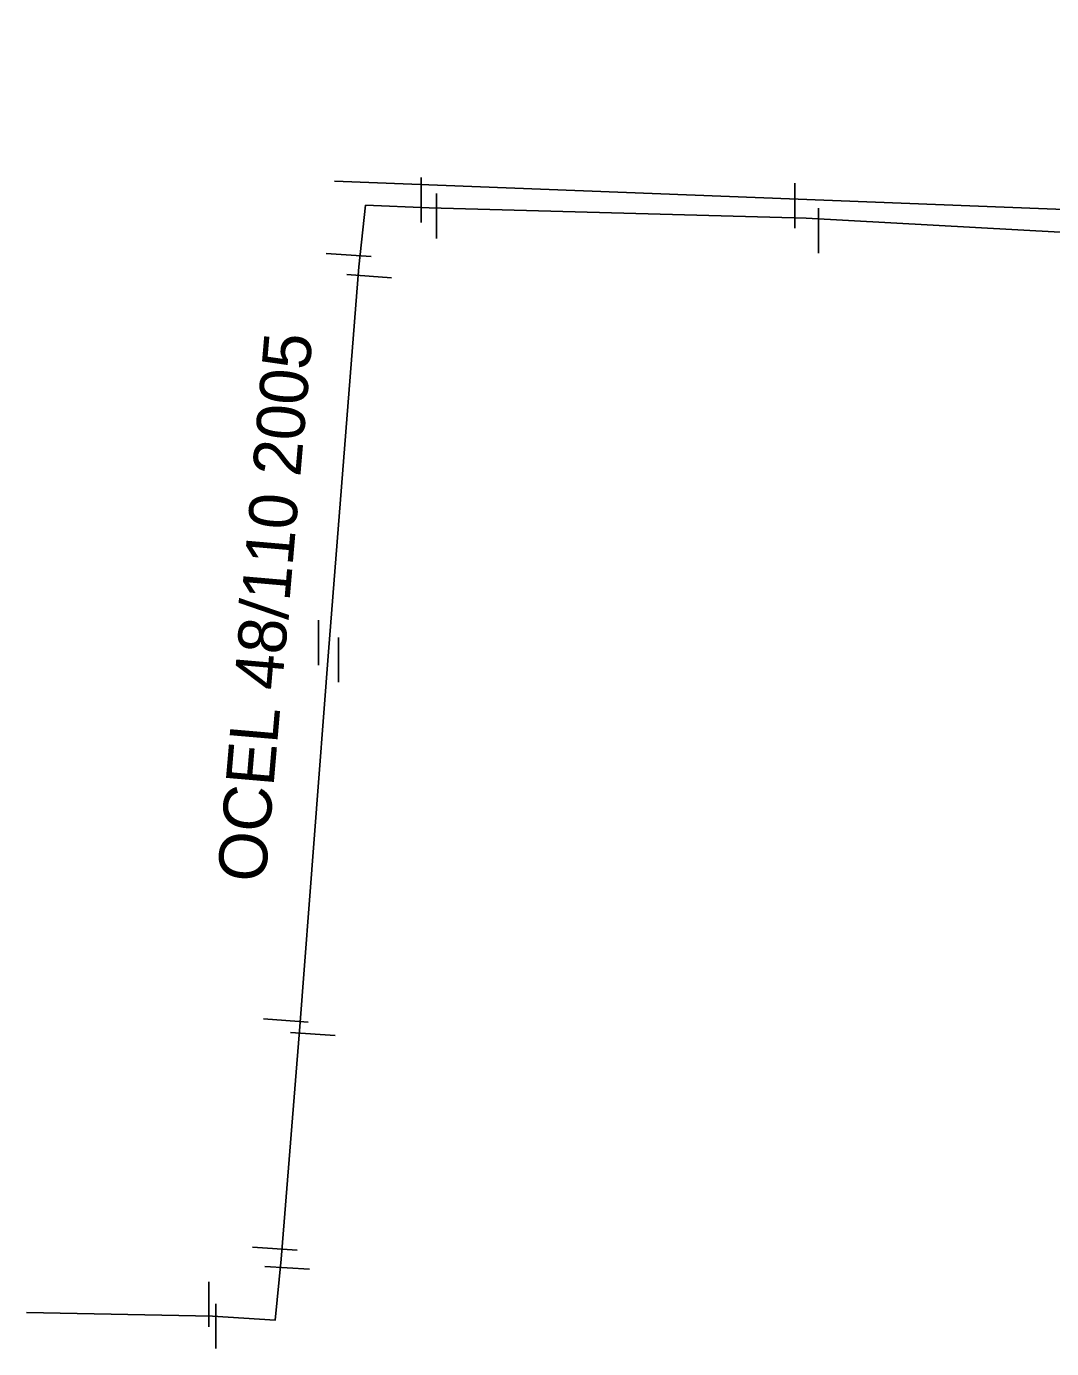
# Model space of a CAD drawing. Extents: x -642943 to -623314, y -1138561 to -1113539.
# Drawn here: x -642466.61 to -642450.62, y -1114240.29 to -1114219.65 of the extents above; entities that cross this region are included whole.
import ezdxf

# ---------------------------------------------------------------- set-up
doc = ezdxf.new("R2010")
doc.units = 0
for name, color, linetype in [('horkovod dimenze', 7, 'Continuous'), ('horkovod předisol', 7, 'Continuous'), ('horkovod sváry', 7, 'Continuous'), ('horkovod trasa', 7, 'Continuous'), ('horkovod zrušený', 7, 'Continuous')]:
    doc.layers.add(name, color=color, linetype=linetype)

# ---------------------------------------------------------------- blocks, each defined once
blk = doc.blocks.new('SPH')
at = {"layer": 'horkovod sváry'}
blk.add_line((0, -0.035), (0, 0.035), dxfattribs=at)

msp = doc.modelspace()

# ---------------------------------------------------------------- linework, layer by layer
at = {"layer": 'horkovod předisol'}
msp.add_lwpolyline([(-642429.336, -1114221.551), (-642435.851, -1114220.861), (-642441.855, -1114220.239), (-642447.001, -1114219.736), (-642448.022, -1114219.652), (-642448.127, -1114220.936), (-642448.293, -1114223.008), (-642449.161, -1114222.938), (-642454.446, -1114222.645), (-642460.326, -1114222.484), (-642461.319, -1114222.442), (-642461.424, -1114223.406), (-642461.898, -1114229.416), (-642462.345, -1114235.265), (-642462.639, -1114238.894), (-642462.73, -1114239.846), (-642463.71, -1114239.783), (-642466.611, -1114239.727)], dxfattribs=at)
at = {"layer": 'horkovod trasa'}
msp.add_lwpolyline([(-642429.336, -1114221.551), (-642435.851, -1114220.861), (-642441.855, -1114220.239), (-642447.001, -1114219.736), (-642448.022, -1114219.652), (-642448.127, -1114220.936), (-642448.293, -1114223.008), (-642449.161, -1114222.938), (-642454.446, -1114222.645), (-642460.326, -1114222.484), (-642461.319, -1114222.442), (-642461.424, -1114223.406), (-642461.898, -1114229.416), (-642462.345, -1114235.265), (-642462.639, -1114238.894), (-642462.73, -1114239.846), (-642463.71, -1114239.783), (-642466.611, -1114239.727)], dxfattribs=at)
at = {"layer": 'horkovod zrušený'}
msp.add_line((-642461.803, -1114222.066), (-642443.097, -1114222.796), dxfattribs=at)

# ---------------------------------------------------------------- block references
at = {"layer": 'horkovod sváry', "xscale": 10, "yscale": 10}
for p in [(-642460.454, -1114222.36), (-642454.624, -1114222.45), (-642460.214, -1114222.61), (-642454.254, -1114222.84), (-642462.054, -1114229.27), (-642461.744, -1114229.54), (-642463.764, -1114239.6), (-642463.654, -1114239.94)]:
    msp.add_blockref('SPH', p, dxfattribs=at)
at = {"layer": 'horkovod sváry'}
for p, xscale, yscale, rotation in [((-642461.584, -1114223.22), 10.000005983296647, 10.000005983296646, 86.0928213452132), ((-642461.264, -1114223.55), 9.999985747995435, 9.999985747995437, 85.84032383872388), ((-642462.564, -1114235.17), 10.000001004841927, 10.000001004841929, -94.15351711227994), ((-642462.144, -1114235.38), 9.99998144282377, 9.999981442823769, -94.00186272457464), ((-642462.734, -1114238.73), 9.999996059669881, 9.999996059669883, -93.80316006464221), ((-642462.544, -1114239.03), 10.000003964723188, 10.000003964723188, -93.19637613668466)]:
    msp.add_blockref('SPH', p, dxfattribs=dict(at, xscale=xscale, yscale=yscale, rotation=rotation))

# ---------------------------------------------------------------- texts
at = {"layer": 'horkovod dimenze'}
msp.add_text('OCEL 48/110 2005', height=0.74999, rotation=85.0596, dxfattribs=at).set_placement((-642462.887, -1114233.027))

doc.saveas('drawing.dxf')
